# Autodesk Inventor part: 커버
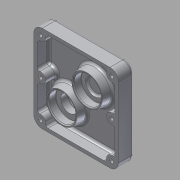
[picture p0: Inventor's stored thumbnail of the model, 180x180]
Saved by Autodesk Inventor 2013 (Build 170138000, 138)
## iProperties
Created: 2015-10
Part Number: 커버
Material: 알루미늄 6061
Document SubType Name: Modeling
Designer: mduedu
Density: 1 g/cm^3
Mass: 93.7286 g
Surface Area: 401.286 cm^2
Volume: 93.7286 cm^3
Author: mduedu
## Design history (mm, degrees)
sketch "스케치1"
  geometry: L1 (-50, -51.5)-(50, -51.5); L2 (50, -51.5)-(50, 51.5); L3 (50, 51.5)-(-50, 51.5); L4 (-50, 51.5)-(-50, -51.5); L5 (-50, -51.5)-(50, 51.5); L6 (50, -51.5)-(-50, 51.5); 1 further point
  constraints: 12 end point, 2 midpoint, 2 parallel, 1 horizontal, 1 perpendicular
  dimensions: "d0" = 100 distance of L3.end L2.end; "d1" = 103 distance of L2.end L1.end
extrude "돌출1" new body sketch "스케치1" distance "d2" = 18; taper "d3" = 0 deg
fillet "모깎기1" dims "d4" = 10
fillet "모깎기2" dims "d5" = 3
feature "쉘1" dims "d6" = 4
sketch "스케치2"
  geometry: L1 (40, 51.5)-(-40, 51.5) reference; L2 (50, -41.5)-(50, 41.5) reference; L3 (-40, -51.5)-(40, -51.5) reference; L4 (-50, 41.5)-(-50, -41.5) reference; L5 (-50, 0)-(50, 0); L6 (0, 51.5)-(0, -51.5); C1 r 6 at (-42, 43.5); C2 r 6 at (-42, 0); C3 r 6 at (-42, -43.5); C4 r 6 at (42, -43.5); C5 r 6 at (42, 0); C6 r 6 at (42, 43.5); 1 further point
  constraints: 6 centre point, 4 end point, 4 midpoint, 4 symmetric about line, 1 equal radius, 1 point on line, 1 vertical alignment, 4 other
  dimensions: "d7" = 12 diameter of C1; "d8" = 8 distance from line of C1.centre L1; "d9" = 8 distance from line of C1.centre L4
extrude "돌출2" join sketch "스케치2" stored distance "d10" = 0; taper "d11" = 0 deg
fillet "모깎기3" dims "d12" = 3
fillet "모깎기4" dims "d13" = 3
sketch "스케치3"
  geometry: A1 r 6 centre (42, 43.5) between (36.037, 44.167) and (42.667, 37.537) reference; A2 r 6 centre (42, 0) between (42.667, 5.963) and (42.667, -5.963) reference; A3 r 6 centre (42, -43.5) between (42.667, -37.537) and (36.037, -44.167) reference; A4 r 6 centre (-42, -43.5) between (-36.037, -44.167) and (-42.667, -37.537) reference; A5 r 6 centre (-42, 0) between (-42.667, -5.963) and (-42.667, 5.963) reference; A6 r 6 centre (-42, 43.5) between (-42.667, 37.537) and (-36.037, 44.167) reference; 7 further points
  constraints: 6 coincident
hole "구멍1" sketch "스케치3" at (-42, 43.5), (-42, 0), (-42, -43.5), (42, -43.5), (42, 0), (42, 43.5) diameter "d14" = 4.5; stored, may be unused: countersink angle "d18" = 90 deg, drill point angle "d20" = 118 deg; dims "d15" = 6, "d16" = 8, "d17" = 4.4, "d19" = 8
sketch "스케치4"
  geometry: L1 (83.056, 3)-(83.056, 86) reference; L2 (73.056, 96)-(-6.944, 96) reference; C1 r 20 at (43.056, 56); 1 further point
  constraints: 1 centre point
  dimensions: "d21" = 40 diameter of C1; "d22" = 40 distance from line of C1.centre L1; "d23" = 40 distance from line of C1.centre L2
extrude "돌출3" join sketch "스케치4" distance "d24" = 11; taper "d25" = -10 deg
hole "구멍2" diameter "d28" = 22; stored, may be unused: countersink angle "d32" = 90 deg, drill point angle "d34" = 0 deg; dims "d29" = 6, "d30" = 32, "d31" = 9, "d33" = 11, "d35" = 10, "d36" = 10
sketch "스케치5"
  geometry: L1 (-40, -51.5)-(40, -51.5) reference; L2 (50, -41.5)-(50, 41.5) reference; C1 r 25 at (20, -21.5); 1 further point
  constraints: 1 centre point
  dimensions: "d37" = 50 diameter of C1; "d40" = 30 distance from line of C1.centre L1; "d41" = 30 distance from line of C1.centre L2
extrude "돌출4" join sketch "스케치5" distance "d42" = 15; taper "d43" = -10 deg
sketch "스케치6"
  geometry: C1 r 25 at (13.056, 23) reference; C2 r 20 at (13.056, 23); 1 further point
  constraints: 1 centre point, 1 coincident
  dimensions: "d44" = 40 diameter of C2
extrude "돌출5" join sketch "스케치6" distance "d45" = 11; taper "d46" = -10 deg
hole "구멍3" diameter "d49" = 20; stored, may be unused: countersink angle "d53" = 90 deg, drill point angle "d55" = 118 deg; dims "d47" = 10, "d48" = 10, "d50" = 6, "d51" = 32, "d52" = 9, "d54" = 11
hole "구멍4" diameter "d58" = 24; stored, may be unused: countersink angle "d62" = 90 deg, drill point angle "d64" = 0 deg; dims "d56" = 10, "d57" = 10, "d59" = 6, "d60" = 28, "d61" = 11, "d63" = 13
chamfer "모따기1" distance "d65" = 1; stored, may be unused: second distance "d66" = 2, angle "d67" = 45 deg
sketch "스케치7" dims "d68" = 36
  geometry: C1 r 25 at (0, 0) reference; 3 further points
  constraints: 2 vertical alignment, 1 coincident, 2 other
hole "구멍5" sketch "스케치7" at (0, 18) diameter "d69" = 2.459; stored, may be unused: countersink angle "d73" = 90 deg, drill point angle "d75" = 118 deg; dims "d70" = 8, "d71" = 28, "d72" = 11, "d74" = 10
sketch "스케치8"
  geometry: L1 (-50, 41.5)-(-50, -41.5) reference; L2 (40, 51.5)-(-40, 51.5) reference; 2 further points
  constraints: 1 other
  dimensions: "d79" = 50 distance from line of point (0, 26.5) L1; "d80" = 25 distance from line of point (0, 26.5) L2
feature "엠보싱1" sketch "스케치8" dims "d0" = 100, "d1" = 103, "d5" = 3, "d81" = 0.5, "d82" = 0
fillet "모깎기5" dims "d83" = 3
fillet "모깎기6" dims "d84" = 3
fillet "모깎기7" dims "d85" = 3
fillet "모깎기8" dims "d86" = 0.3
fillet "모깎기9" dims "d87" = 3
node "솔리드1"
pattern_circular "원형 패턴1" dims angle "d77" = 360 deg
